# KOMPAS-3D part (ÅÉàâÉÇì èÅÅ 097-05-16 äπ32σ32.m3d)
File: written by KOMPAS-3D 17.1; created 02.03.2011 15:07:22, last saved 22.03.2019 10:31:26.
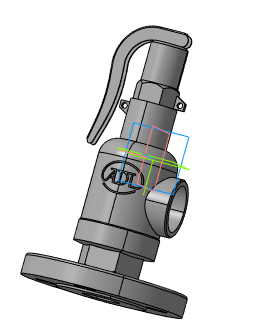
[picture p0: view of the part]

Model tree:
1. Плоскость XY
2. Плоскость ZX
3. Плоскость ZY
4. Ось X
5. Ось Y
6. Ось Z
7. Начало координат
8. Операция без истории:2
